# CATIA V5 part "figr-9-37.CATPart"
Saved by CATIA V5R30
Part number: Part1
Bounding box of the stored display mesh (mm): x 0 to 200, y -70 to 70, z -70 to 70
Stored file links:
  D:\PROJECTS\CATIA V56R 2020\Resources\Parts File\c09_catia_v5_6r2020_prt\figr-9-37.CATPart
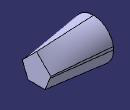
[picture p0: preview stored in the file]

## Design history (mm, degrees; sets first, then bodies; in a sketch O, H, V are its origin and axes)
Set1
  Plane1: type Offset, RefPlane yz-plane, Offset 200
Body1 (main body)
  Sketch1 on yz-plane, origin (0, 0, 0), H (0, 1, 0), V (0, 0, 1)
    circle A1 centre (0, 0) radius 70
    point P1 (70, 0)
    point P2 (-48.9898, -50)
    point P3 (48.9898, -50)
    point P4 (69.282, 10)
    point P5 (-69.282, 10)
    point P6 (0, 70)
    radius A1 = 70
    coincidence: A1 P1, P1 H, P2 A1, P3 A1, P4 A1, P5 A1, P6 V
  Sketch2 on Plane1, origin (200, 0, 0), H (0, 1, 0), V (0, 0, 1)
    point P1 (-30, -40)
    line L1 (-30, -40) -> (30, -40)
    point P2 (30, -40)
    line L2 (30, -40) -> (50, 10)
    point P3 (50, 10)
    line L3 (50, 10) -> (0, 60)
    point P4 (0, 60)
    line L4 (0, 60) -> (-50, 10)
    point P5 (-50, 10)
    line L5 (-50, 10) -> (-30, -40)
    horizontal: L1 H
    coincidence: P4 V
    symmetry: P3 P5 V, P2 P1 V
  Loft1: Sections (edge of Sketch1; Sketch2), SectionCouplingPoints ({coupling CouplingPoints (vertex of Sketch1; vertex [element of Sketch2 | element of Sketch2])}; {coupling CouplingPoints (vertex of Sketch1; vertex [element of Sketch2 | element of Sketch2])}; {coupling CouplingPoints (vertex of Sketch1; vertex [element of Sketch2 | element of Sketch2])}; {coupling CouplingPoints (vertex of Sketch1; vertex [element of Sketch2 | element of Sketch2])})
